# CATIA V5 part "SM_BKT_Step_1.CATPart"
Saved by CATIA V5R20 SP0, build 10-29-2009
Part number: SM_BKT
Bounding box of the stored display mesh (mm): x 0 to 137.579, y 0 to 228.383, z 0 to 43
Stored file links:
  C:\Users\CAS\Desktop\GSD_Class_Parts\SM_BKT_Step_1.CATPart
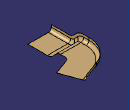
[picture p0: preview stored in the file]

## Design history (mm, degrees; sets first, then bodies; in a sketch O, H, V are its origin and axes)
Set1 "CONST_GEO"
  Point1: type OnCurve, Support Sketch1, Length 10
Set2 "Inputs"
  Sketch1 "Flange Sketch" on xy-plane, origin (0, 0, 0), H (1, 0, 0), V (0, 1, 0)
    point P1 (0, -20)
    line L1 (0, -20) -> (0, 125)
    arc A1 centre (90, 125) radius 90 from (0, 125) to (59.2182, 209.5723) cw
    point P3 (90, 125)
    line L2 (59.2182, 209.5723) -> (120.2982, 231.8036)
    radius A1 = 90
    distance H P3 = 125
    angle L1 L2 = 110
    length L2 = 65
    distance H P1 = 20
    coincidence: P1 V
    vertical: L1 V
    tangency: A1 L1, A1 L2
  Sketch2 "Main Body Sketch" on yz-plane, origin (0, 0, 0), H (0, 1, 0), V (0, 0, 1)
    point P1 (-20, 0)
    line L1 (-20, 0) -> (75, 0)
    point P2 (75, 0)
    line L2 (75, 0) -> (100, 25)
    line L3 (100, 25) -> (275, 25)
    reference intersected line E1 through (0, 0) direction (0, 1) from zx-plane
    distance V P1 = 20
    angle L1 L2 = 45
    distance L1 L3 = 25
    distance E1 P2 = 75
    length L3 = 175
    horizontal: L1 H, L3 H
    coincidence: H L1
Set3 "Spliting Elements"
  Plane1: type Normal, Curve Sketch1, RefPoint Point1
  Offset1: Offset Extrude2, Length 78
  Extract1: ExtractElem edge [face of Fillet3 | face of Extrude2 from Sketch1.L1]
  CurvePar1: Offset Extract1, Offset2 0, Offset1 8, Support Fillet3
Set4 "Final"
  Split1: ToCut Fillet3, Cutting (CurvePar1; Plane1; Offset1; zx-plane)
Set5 "Operations"
  Extrude1: Lim1 300, Lim2 300, Element1 Sketch2
  Fillet1: radius 25, on edge [face of Extrude1 from Sketch2.L2 | face of Extrude1 from Sketch2.L1]
  Fillet2: radius 20, on edge [face of Extrude1 from Sketch2.L3 | face of Extrude1 from Sketch2.L2]
  Extrude2: Lim1 300, Lim2 300, Element1 Sketch1
  Fillet3: type BiTangent, Element1 Fillet2, Element2 Extrude2, Radius 10
Body1 (main body)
